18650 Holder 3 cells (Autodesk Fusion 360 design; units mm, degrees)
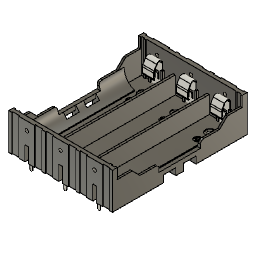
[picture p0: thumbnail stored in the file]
description: STEP AP214
part number: arrangementsContainer
description: NONE
named bodies: "Body1"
